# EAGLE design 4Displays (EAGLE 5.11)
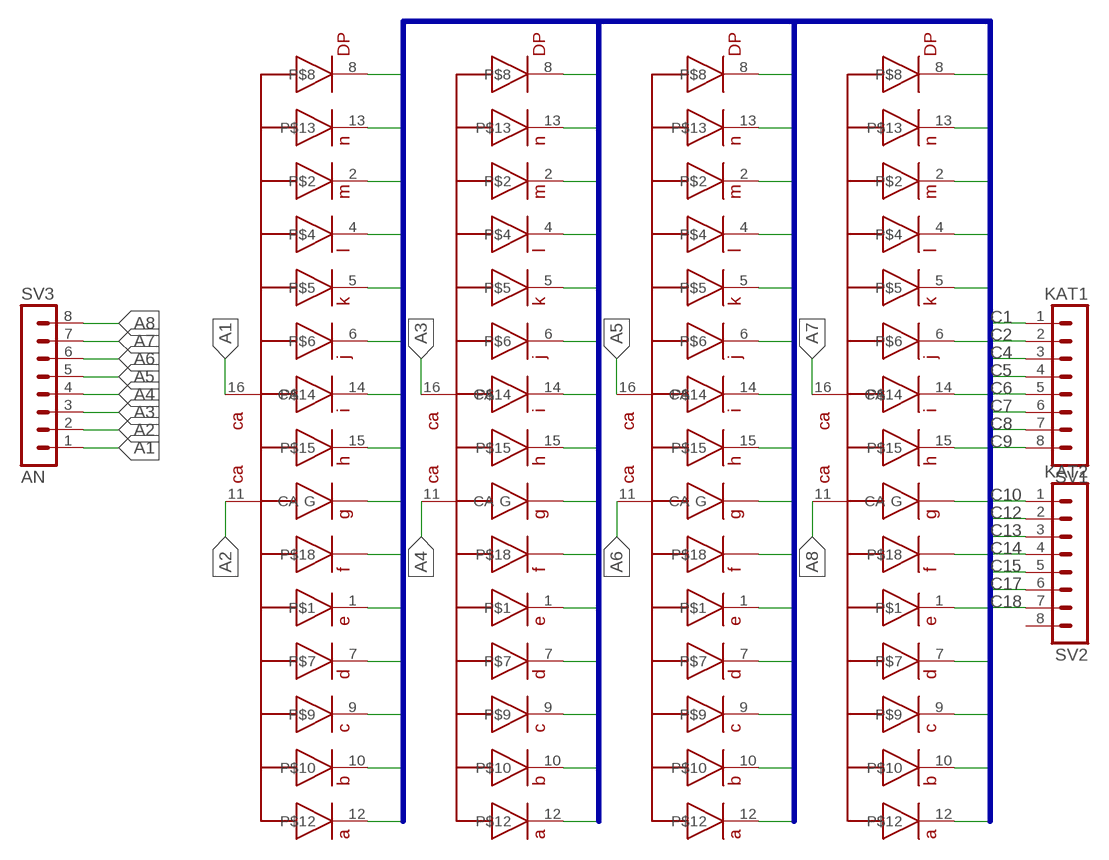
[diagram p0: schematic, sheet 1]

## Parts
DSP1  PDA54-11PDA54-11EWA  [PD_54-11]
DSP2  PDA54-11PDA54-11EWA  [PD_54-11]
DSP3  PDA54-11PDA54-11EWA  [PD_54-11]
DSP4  PDA54-11PDA54-11EWA  [PD_54-11]
SV1  KAT1  MA08-1  [MA08-1]
SV2  KAT2  MA08-1  [MA08-1]
SV3  AN  MA08-1  [MA08-1]

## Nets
A1: DSP1.16(CA) SV3.1
A2: DSP1.11(CA) SV3.2
A3: DSP2.16(CA) SV3.3
A4: DSP2.11(CA) SV3.4
A5: DSP3.16(CA) SV3.5
A6: DSP3.11(CA) SV3.6
A7: DSP4.16(CA) SV3.7
A8: DSP4.11(CA) SV3.8
C1: DSP1.1 DSP2.1 DSP3.1 DSP4.1 SV1.1
C2: DSP1.2 DSP2.2 DSP3.2 DSP4.2 SV1.2
C4: DSP1.4 DSP2.4 DSP3.4 DSP4.4 SV1.3
C5: DSP1.5 DSP2.5 DSP3.5 DSP4.5 SV1.4
C6: DSP1.6 DSP2.6 DSP3.6 DSP4.6 SV1.5
C7: DSP1.7 DSP2.7 DSP3.7 DSP4.7 SV1.6
C8: DSP1.8 DSP2.8 DSP3.8 DSP4.8 SV1.7
C9: DSP1.9 DSP2.9 DSP3.9 DSP4.9 SV1.8
C10: DSP1.10 DSP2.10 DSP3.10 DSP4.10 SV2.1
C12: DSP1.12 DSP2.12 DSP3.12 DSP4.12 SV2.2
C13: DSP1.13 DSP2.13 DSP3.13 DSP4.13 SV2.3
C14: DSP1.14 DSP2.14 DSP3.14 DSP4.14 SV2.4
C15: DSP1.15 DSP2.15 DSP3.15 DSP4.15 SV2.5
C17: DSP1.17(G) DSP2.17(G) DSP3.17(G) DSP4.17(G) SV2.6
C18: DSP1.18 DSP2.18 DSP3.18 DSP4.18 SV2.7
Unconnected: SV2.8

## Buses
C[1..18]

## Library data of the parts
DSP1-DSP4 = Kingbright PDx54-11EWA:PDA54-11: Comon anode
SV1-SV3 = con-lstb:MA08-1: PIN HEADER; OC_FARNELL: unknown; OC_NEWARK: unknown

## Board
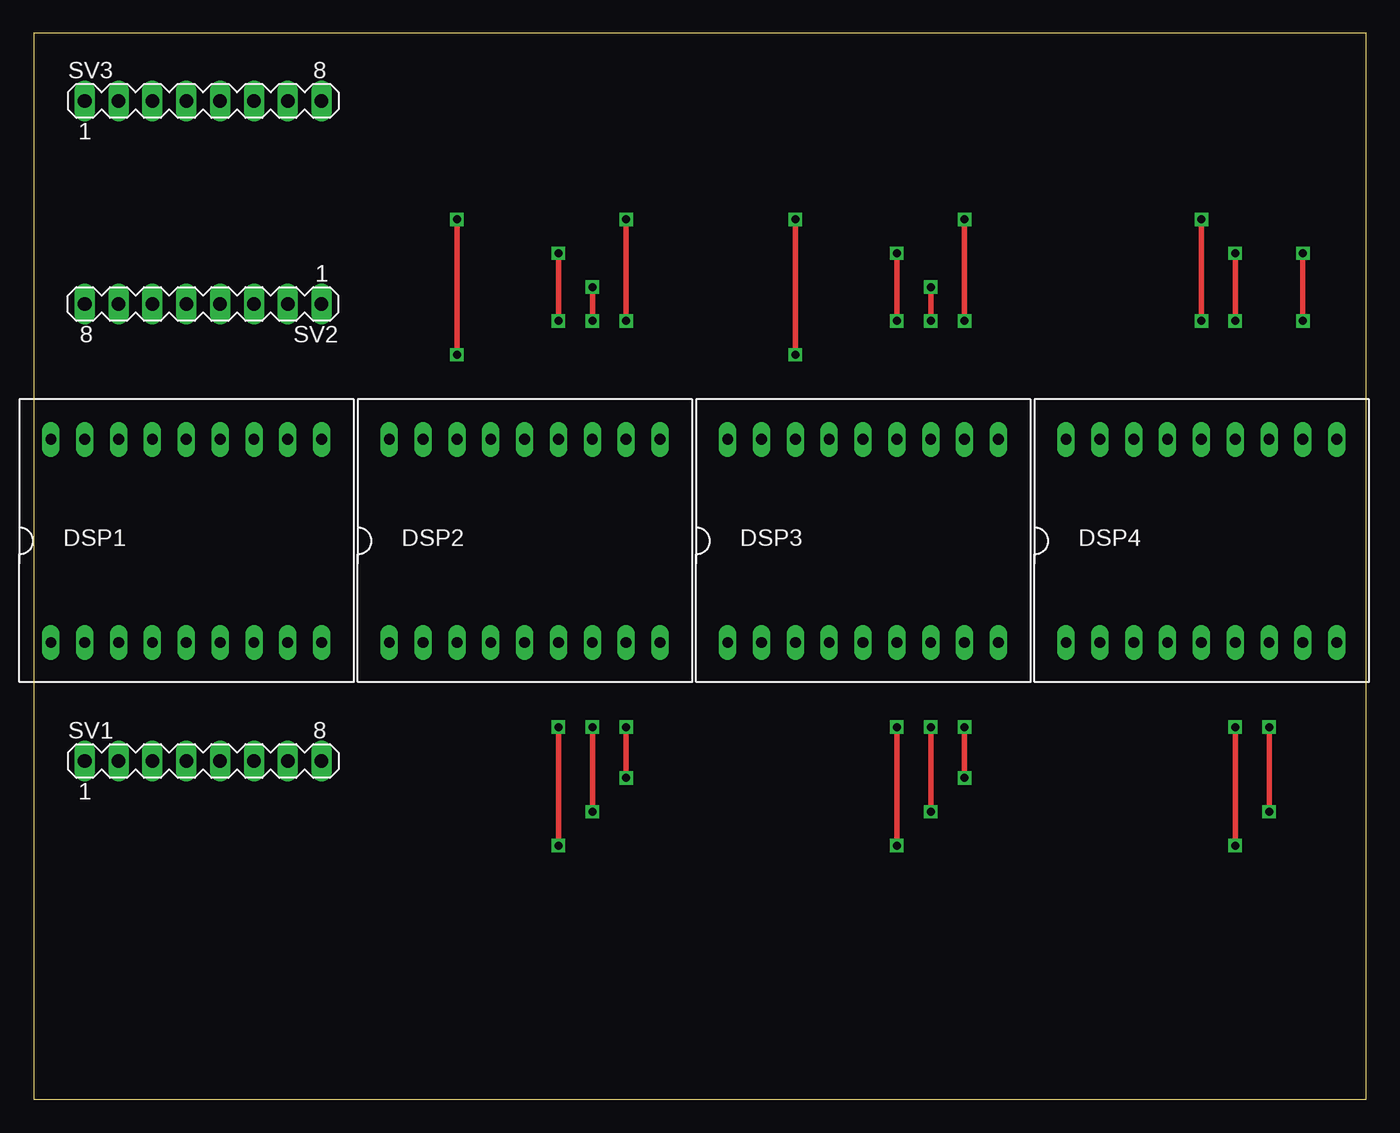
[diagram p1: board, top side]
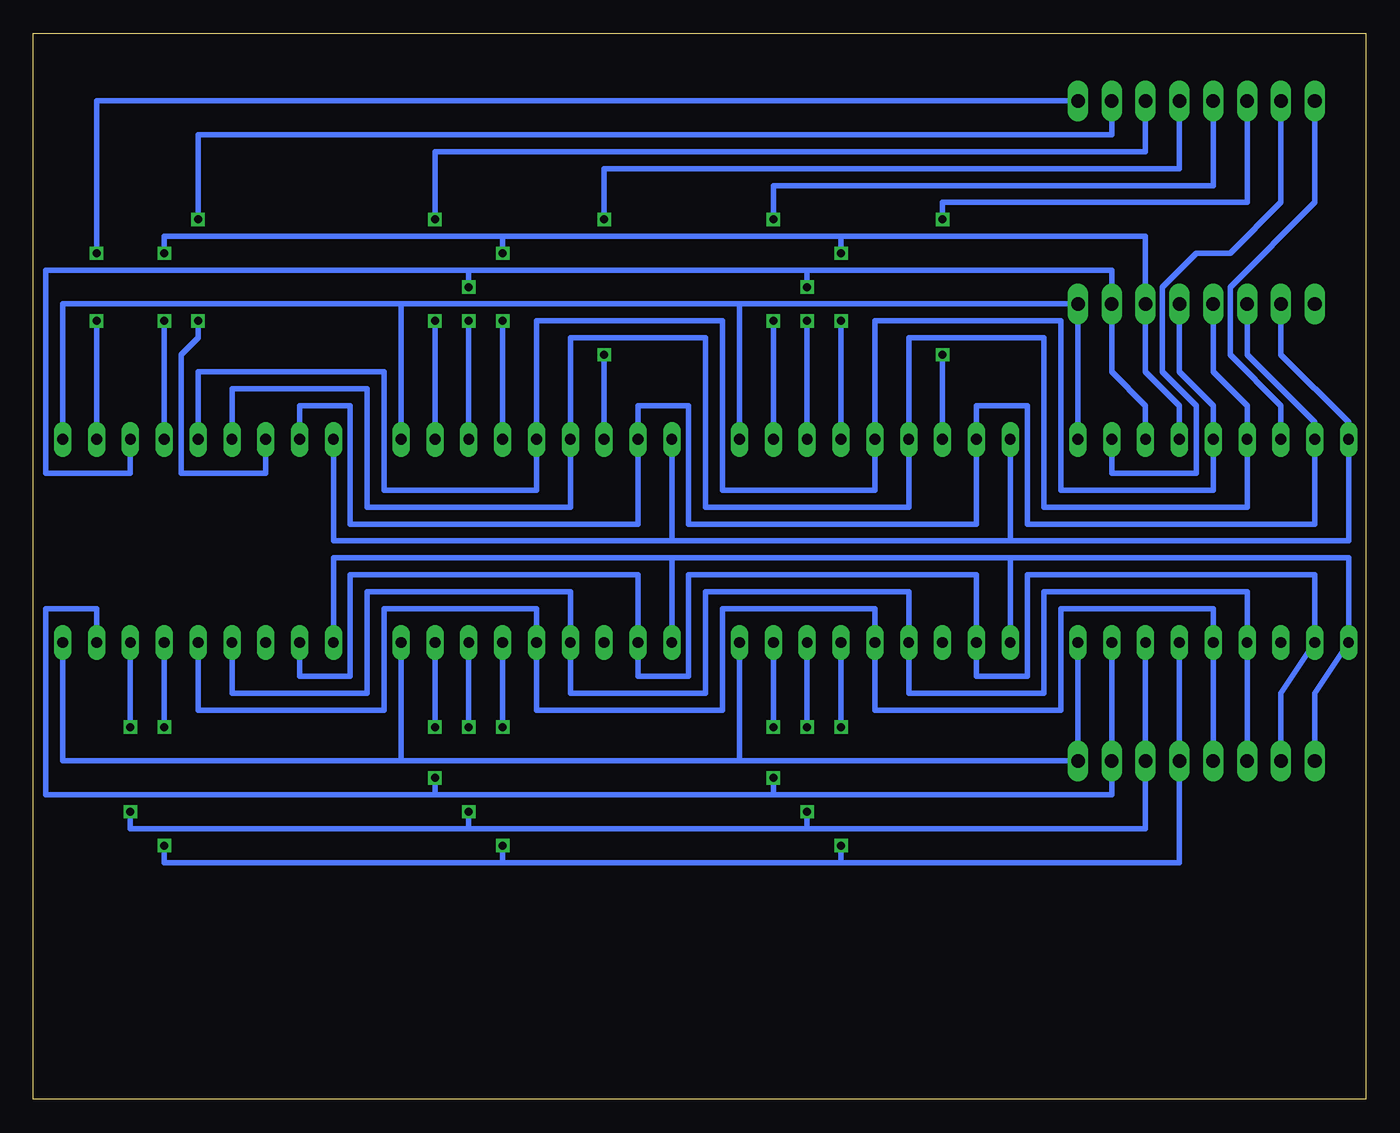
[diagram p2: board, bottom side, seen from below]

Size 100 x 80 mm. Coordinates in mm from the lower left corner, seen from the top.
Outline: 0,0 100,0 100,80 0,80 0,0
Copper layers (1*16): Top 0.035mm / dielectric 1.5mm / Bottom 0.035mm
Design rules "default": minimum track width 10mil, minimum drill 24mil, track to track 8mil, track to pad 8mil, pad to pad 8mil, via to via 8mil, smd to smd 8mil, copper to edge 40mil, drill to drill 8mil, minimum pad ring 10mil, minimum via ring 8mil, stop-mask expansion 4mil, vias tented up to drill 0mil, thermal gap 10mil

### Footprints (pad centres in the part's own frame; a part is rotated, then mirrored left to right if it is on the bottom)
PD_54-11 = drill 0.813 long: 1 -10.16,-7.62; 2 -7.62,-7.62; 3 -5.08,-7.62; 4 -2.54,-7.62; 5 0,-7.62; 6 2.54,-7.62; 7 5.08,-7.62; 8 7.62,-7.62; 9 10.16,-7.62; 10 10.16,7.62; 11 7.62,7.62; 12 5.08,7.62; 13 2.54,7.62; 14 0,7.62; 15 -2.54,7.62; 16 -5.08,7.62; 17 -7.62,7.62; 18 -10.16,7.62
MA08-1 = drill 1.016 long: 1 -8.89,0; 2 -6.35,0; 3 -3.81,0; 4 -1.27,0; 5 1.27,0; 6 3.81,0; 7 6.35,0; 8 8.89,0

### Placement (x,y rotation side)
DSP1  11.43,41.91 0 top
DSP2  36.83,41.91 0 top
DSP3  62.23,41.91 0 top
DSP4  87.63,41.91 0 top
SV1  12.7,25.4 0 top
SV2  12.7,59.69 180 top
SV3  12.7,74.93 0 top

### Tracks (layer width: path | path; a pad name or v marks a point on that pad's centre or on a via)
A1
  Bottom 0.406: DSP1.16 6.35,52.07 10.16,55.88 10.16,60.96 3.81,67.31 SV3.1
A2
  Bottom 0.406: DSP1.11 19.05,46.99 12.7,46.99 12.7,52.07 15.24,54.61 15.24,60.96 12.7,63.5 10.16,63.5 6.35,67.31 SV3.2
A3  (via drill 0.6)
  Top 0.406: v31.75,55.88 v31.75,66.04
  Bottom 0.406: DSP2.16 v31.75,55.88 | v31.75,66.04 31.75,67.31 8.89,67.31 SV3.3
A4  (via drill 0.6)
  Top 0.406: v44.45,58.42 v44.45,66.04
  Bottom 0.406: DSP2.11 v44.45,58.42 | v44.45,66.04 44.45,68.58 11.43,68.58 SV3.4
A5  (via drill 0.6)
  Top 0.406: v57.15,55.88 v57.15,66.04
  Bottom 0.406: DSP3.16 v57.15,55.88 | v57.15,66.04 57.15,69.85 13.97,69.85 SV3.5
A6  (via drill 0.6)
  Top 0.406: v69.85,58.42 v69.85,66.04
  Bottom 0.406: DSP3.11 v69.85,58.42 | v69.85,66.04 69.85,71.12 16.51,71.12 SV3.6
A7  (via drill 0.6)
  Top 0.406: v87.63,58.42 v87.63,66.04
  Bottom 0.406: DSP4.16 82.55,46.99 88.9,46.99 88.9,55.88 87.63,57.15 v87.63,58.42 | v87.63,66.04 87.63,72.39 19.05,72.39 SV3.7
A8  (via drill 0.6)
  Top 0.406: v95.25,63.5 v95.25,58.42
  Bottom 0.406: SV3.8 95.25,74.93 v95.25,63.5 | v95.25,58.42 DSP4.11
C1
  Bottom 0.406: SV1.1 3.81,30.48 DSP1.1 1.27,40.64 26.67,40.64 | 26.67,40.64 DSP2.1 | 52.07,40.64 DSP3.1 | 26.67,40.64 52.07,40.64 | DSP4.1 77.47,40.64 52.07,40.64
C2
  Bottom 0.406: SV1.2 6.35,30.48 DSP1.2 3.81,39.37 25.4,39.37 25.4,31.75 29.21,31.75 DSP2.2 29.21,39.37 50.8,39.37 50.8,31.75 54.61,31.75 DSP3.2 54.61,39.37 76.2,39.37 76.2,31.75 80.01,31.75 DSP4.2
C4
  Bottom 0.406: SV1.3 DSP1.4 8.89,38.1 24.13,38.1 24.13,30.48 34.29,30.48 DSP2.4 34.29,38.1 49.53,38.1 49.53,30.48 59.69,30.48 DSP3.4 59.69,38.1 74.93,38.1 74.93,30.48 85.09,30.48 DSP4.4
C5
  Bottom 0.406: SV1.4 DSP1.5 11.43,36.83 22.86,36.83 22.86,29.21 36.83,29.21 DSP2.5 36.83,36.83 48.26,36.83 48.26,29.21 62.23,29.21 DSP3.5 62.23,36.83 73.66,36.83 73.66,29.21 87.63,29.21 DSP4.5
C6  (via drill 0.6)
  Top 0.406: v90.17,19.05 v90.17,27.94 | v64.77,19.05 v64.77,27.94 | v39.37,19.05 v39.37,27.94
  Bottom 0.406: DSP1.6 SV1.5 13.97,17.78 39.37,17.78 | v90.17,27.94 DSP4.6 | v90.17,19.05 90.17,17.78 64.77,17.78 | 39.37,17.78 64.77,17.78 | v64.77,27.94 DSP3.6 | 64.77,17.78 v64.77,19.05 | v39.37,27.94 DSP2.6 | 39.37,17.78 v39.37,19.05
C7  (via drill 0.6)
  Top 0.406: v92.71,21.59 v92.71,27.94 | v67.31,21.59 v67.31,27.94 | v41.91,21.59 v41.91,27.94
  Bottom 0.406: DSP1.7 SV1.6 16.51,20.32 41.91,20.32 | v92.71,27.94 DSP4.7 | v92.71,21.59 92.71,20.32 67.31,20.32 | 41.91,20.32 67.31,20.32 | v67.31,27.94 DSP3.7 | 67.31,20.32 v67.31,21.59 | v41.91,27.94 DSP2.7 | 41.91,20.32 v41.91,21.59
C8  (via drill 0.6)
  Top 0.406: v44.45,24.13 v44.45,27.94 | v69.85,24.13 v69.85,27.94
  Bottom 0.406: DSP1.8 SV1.7 19.05,22.86 44.45,22.86 | DSP4.8 95.25,36.83 99.06,36.83 99.06,22.86 69.85,22.86 | 44.45,22.86 69.85,22.86 | 44.45,22.86 v44.45,24.13 | v44.45,27.94 DSP2.8 | v69.85,27.94 DSP3.8 | 69.85,22.86 v69.85,24.13
C9
  Bottom 0.406: DSP1.9 SV1.8 46.99,25.4 | 46.99,25.4 DSP2.9 | 72.39,25.4 DSP3.9 | 46.99,25.4 72.39,25.4 | DSP4.9 97.79,25.4 72.39,25.4
C10
  Bottom 0.406: DSP1.10 SV2.1 46.99,59.69 | DSP4.10 97.79,59.69 72.39,59.69 | 46.99,59.69 72.39,59.69 | 72.39,59.69 DSP3.10 | 46.99,59.69 DSP2.10
C12  (via drill 0.6)
  Top 0.406: v67.31,60.96 v67.31,58.42 | v41.91,60.96 v41.91,58.42
  Bottom 0.406: DSP1.12 16.51,52.07 19.05,54.61 SV2.2 19.05,62.23 41.91,62.23 | DSP4.12 92.71,46.99 99.06,46.99 99.06,62.23 67.31,62.23 | 41.91,62.23 67.31,62.23 | v67.31,58.42 DSP3.12 | 67.31,62.23 v67.31,60.96 | v41.91,58.42 DSP2.12 | 41.91,62.23 v41.91,60.96
C13  (via drill 0.6)
  Top 0.406: v90.17,63.5 v90.17,58.42 | v64.77,63.5 v64.77,58.42 | v39.37,63.5 v39.37,58.42
  Bottom 0.406: DSP1.13 13.97,52.07 16.51,54.61 SV2.3 16.51,64.77 39.37,64.77 | v90.17,58.42 DSP4.13 | v90.17,63.5 90.17,64.77 64.77,64.77 | 39.37,64.77 64.77,64.77 | v64.77,58.42 DSP3.13 | 64.77,64.77 v64.77,63.5 | v39.37,58.42 DSP2.13 | 39.37,64.77 v39.37,63.5
C14
  Bottom 0.406: SV2.4 13.97,54.61 11.43,52.07 DSP1.14 11.43,45.72 22.86,45.72 22.86,58.42 36.83,58.42 DSP2.14 36.83,45.72 48.26,45.72 48.26,58.42 62.23,58.42 DSP3.14 62.23,45.72 73.66,45.72 73.66,54.61 87.63,54.61 DSP4.14
C15
  Bottom 0.406: SV2.5 11.43,54.61 8.89,52.07 DSP1.15 8.89,44.45 24.13,44.45 24.13,57.15 34.29,57.15 DSP2.15 34.29,44.45 49.53,44.45 49.53,57.15 59.69,57.15 DSP3.15 59.69,44.45 74.93,44.45 74.93,53.34 85.09,53.34 DSP4.15
C17
  Bottom 0.406: SV2.6 8.89,55.88 3.81,50.8 DSP1.17 3.81,43.18 25.4,43.18 25.4,52.07 29.21,52.07 DSP2.17 29.21,43.18 50.8,43.18 50.8,52.07 54.61,52.07 DSP3.17 54.61,43.18 76.2,43.18 76.2,52.07 80.01,52.07 DSP4.17
C18
  Bottom 0.406: SV2.7 6.35,55.88 1.27,50.8 DSP1.18 1.27,41.91 26.67,41.91 | 26.67,41.91 DSP2.18 | 52.07,41.91 DSP3.18 | 26.67,41.91 52.07,41.91 | DSP4.18 77.47,41.91 52.07,41.91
